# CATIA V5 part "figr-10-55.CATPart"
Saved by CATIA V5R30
Part number: Part1
Bounding box of the stored display mesh (mm): x -101.896 to 127.212, y -67.72 to 67.298, z 0 to 0
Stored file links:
  D:\PROJECTS\CATIA V56R 2020\Resources\Parts File\c10_catia_v5_6r2020_prt\figr-10-55.CATPart
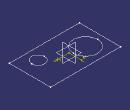
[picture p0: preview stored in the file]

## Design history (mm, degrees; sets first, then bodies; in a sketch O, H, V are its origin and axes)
Body1 (main body)
  Sketch1 on xy-plane, origin (0, 0, 0), H (1, 0, 0), V (0, 1, 0)
    line L1 (-101.8963, 67.298) -> (127.2122, 67.298)
    line L2 (127.2122, 67.298) -> (127.2122, -67.7199)
    line L3 (127.2122, -67.7199) -> (-101.8963, -67.7199)
    line L4 (-101.8963, -67.7199) -> (-101.8963, 67.298)
    horizontal: L1 H, L3 H
    vertical: L2 V, L4 V
  Sketch2 on xy-plane, origin (0, 0, 0), H (1, 0, 0), V (0, 1, 0)
    circle A1 centre (-45.2964, 9.2296) radius 39.3004
    circle A2 centre (71.0804, -29.9585) radius 20.9926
